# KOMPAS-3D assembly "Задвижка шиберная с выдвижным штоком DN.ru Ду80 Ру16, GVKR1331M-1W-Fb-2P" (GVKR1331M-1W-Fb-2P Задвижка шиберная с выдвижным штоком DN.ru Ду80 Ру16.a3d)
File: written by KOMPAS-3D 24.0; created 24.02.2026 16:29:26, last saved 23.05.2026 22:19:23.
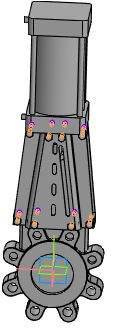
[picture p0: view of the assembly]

Document properties: Автор: R2D2; Полное имя файла: E:\Работа\Зайцев\GVKR1331M-1W-Fb-2P Задвижка шиберная с выдвижным штоком DN.ru Ду50-300 Ру16-10-6 с пневмоприводом\исходные материалы\DN80\GVKR1331M-1W-Fb-2P Задвижка шиберная с выдвижным штоком DN.ru Ду80 Ру16.a3d

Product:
- Component [detail]: Затвор дисковый DN.ru Ду Ру  | qty 1  | pos. 1  | Масса: 18.2; Раздел спецификации: Прочие изделия; Примечание: D050-23732; Автор: R2D2; source file: Задвижка шиберная РЕЗЬБОВОЙ DN.ru Ду Ру.m3d
- Component [detail]: Пневмоцилиндр  | qty 1  | pos. 2  | Масса: 17.894386; Автор: R2D2; source file: Пневмоцилиндр.m3d
- Component [standard]: Hexagon head screw ISO 4017 - М8 x 16  | qty 16  | Масса: 0.012085; Раздел спецификации: Стандартные изделия; Рассекать на разрезах: no
- Component [detail]: лист  | qty 2  | pos. 3  | Масса: 0.899379; Раздел спецификации: Прочие изделия; Примечание: D040-08800; Автор: R2D2; source file: лист.m3d
- Component [detail]: шибер  | qty 1  | pos. 4  | Масса: 0.794721; Раздел спецификации: Прочие изделия; Примечание: D040-08800; Автор: R2D2; source file: шибер.m3d
- Part/product: Задвижка шиберная с выдвижным штоком DN.ru Ду80 Ру16  | designation GVKR1331M-1W-Fb-2P
    Масса: 12
    Раздел спецификации: Прочие изделия
    Примечание: D040-08793

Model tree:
1. Точка:1  (with: Ребро.Отверстие в листовом теле:2)
     X = -34.574; Y = 102.5; Z = 46
2. Точка:2  (with: Ребро.Отверстие в листовом теле:3)
     X = 34.574; Y = 102.5; Z = 46
3. Точка:3  (with: Ребро.Отверстие в листовом теле:4)
     X = 67.6737; Y = 102.5; Z = 27.5
4. Точка:4  (with: Ребро.Отверстие в листовом теле:5)
     X = -49.5061; Y = 276; Z = 27.5
5. Точка:5  (with: Ребро.Отверстие в листовом теле:6)
     X = -12.1867; Y = 276; Z = 46
6. Точка:6  (with: Ребро.Отверстие в листовом теле:7)
     X = 12.1867; Y = 276; Z = 46
7. Точка:7  (with: Ребро.Отверстие в листовом теле:8)
     X = 49.5061; Y = 276; Z = 27.5
8. Массив по точкам:1
9. Экземпляр ( 6 )
10. Экземпляр ( 4 )
11. Экземпляр ( 1 )
12. Экземпляр ( 7 )
13. Экземпляр ( 3 )
14. Экземпляр ( 5 )
15. Экземпляр ( 2 )  (with: Грань.Элемент выдавливания:8, Грань.Отверстие в листовом теле:1, Грань.Линейчатая обечайка:1)
     Ориентация = 2; Ориентация = 2; Ориентация = 2; Ориентация = 2; Ориентация = 2; Ориентация = 2; Ориентация = 2; Ориентация = 2; Ориентация = 2

Expressions: D050-23732; D040-08800
Referenced files in E:\Работа\Зайцев\GVKR1331M-1W-Fb-2P Задвижка шиберная с выдвижным штоком DN.ru Ду50-300 Ру16-10-6 с пневмоприводом\исходные материалы\DN80\: Задвижка шиберная РЕЗЬБОВОЙ DN.ru Ду Ру.m3d, Пневмоцилиндр.m3d, лист.m3d, шибер.m3d
Referenced files in C:\Program Files\ASCON\KOMPAS-3D v24\Libs\PolynomLib\DATA\vault\Methods\Kompas\3D\: PLib_Bolt_1_ISO_1100.m3d
Referenced files in E:\Работа\Зайцев\GVKR1331E-1W-Fb-2P Задвижка шиберная DN.ru Ду50-300 Ру16-10-6\исходные материалы\DN80\: лист.m3d
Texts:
  Hexagon head screw
  BOSimple***PART:17775d1c-e7de-f283-40f0-d40789f7f59e***SHORTLOC:A259_7B16EF33AB1642D2[13;1,25;16;8;-;Undefined]
  Программные изделия  и базы данных
  GVKR1331M-1W-Fb-2P
  Hexagon head screw ISO 4017 - М8 x 16 (1)
  hole1
  hole2
  лист (1)
  лист (2)
  Hexagon head screw ISO 4017 - М8 x 16 (9)
  Hexagon head screw ISO 4017 - М8 x 16 (10)
  Hexagon head screw ISO 4017 - М8 x 16 (11)
  Hexagon head screw ISO 4017 - М8 x 16 (12)
  Hexagon head screw ISO 4017 - М8 x 16 (13)
  Hexagon head screw ISO 4017 - М8 x 16 (14)
  Hexagon head screw ISO 4017 - М8 x 16 (15)
  Hexagon head screw ISO 4017 - М8 x 16 (16)
  Ось Y.Начало координат
  Плоскость ZY.Начало координат
  Плоскость ZX.Начало координат
  Плоскость XY.Начало координат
